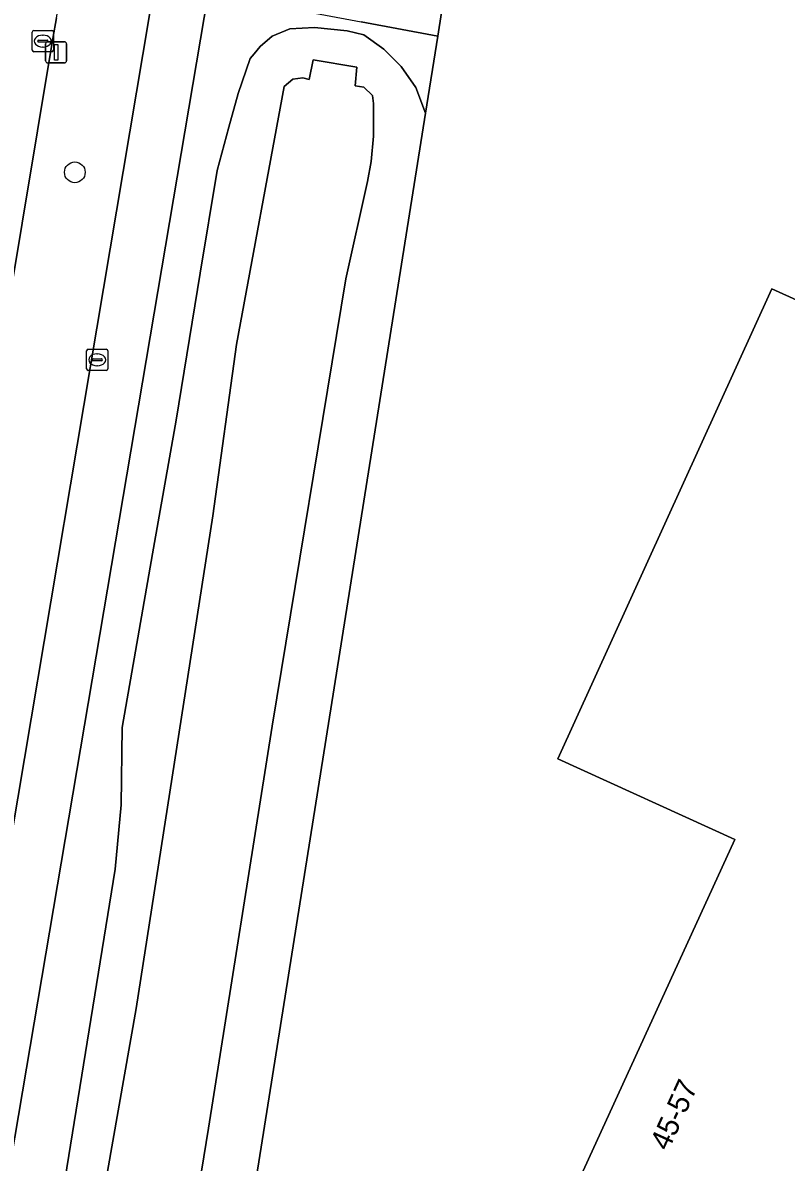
# Model space of a CAD drawing. Extents: x 156141 to 158132, y 385651 to 388333.
# Drawn here: x 156367.7 to 156403.8, y 386609.6 to 386663.4 of the extents above; entities that cross this region are included whole.
import ezdxf

# ---------------------------------------------------------------- set-up
doc = ezdxf.new("R2010")
doc.units = 0
for name, color, linetype in [('IMGEO_Berm_groen', 7, 'Continuous'), ('IMGEO_Boom', 7, 'Continuous'), ('IMGEO_Erf', 7, 'Continuous'), ('IMGEO_Fietspad_gesloten', 7, 'Continuous'), ('IMGEO_Kolk', 7, 'Continuous'), ('IMGEO_Lichtmast', 7, 'Continuous'), ('IMGEO_Muur', 7, 'Continuous'), ('IMGEO_Oever', 7, 'Continuous'), ('IMGEO_Pand', 7, 'Continuous'), ('IMGEO_Pand_nummerreeks', 7, 'Continuous'), ('IMGEO_Rijbaan_lokaal_gesloten', 7, 'Continuous'), ('IMGEO_Rijbaan_lokaal_open', 7, 'Continuous'), ('IMGEO_Rioolput', 7, 'Continuous'), ('IMGEO_Waterloop', 7, 'Continuous')]:
    doc.layers.add(name, color=color, linetype=linetype)

msp = doc.modelspace()

# ---------------------------------------------------------------- linework, layer by layer
at = {"layer": 'IMGEO_Berm_groen'}
for points in [[(156369.305, 386663.658), (156369.141, 386662.678), (156366.222, 386645.225), (156363.399, 386628.51), (156359.75, 386606.622), (156357.341, 386592.608), (156355.257, 386580.281), (156355.517, 386580.234), (156355.483, 386579.181), (156355.759, 386578.249), (156356.674, 386577.611), (156357.605, 386577.179), (156359.068, 386576.796), (156374.013, 386665.695)], [(156376.478, 386664.815), (156361.284, 386575.046)], [(156364.161, 386574.52), (156372.084, 386623.408), (156372.357, 386626.449), (156372.418, 386630.114), (156373.848, 386638.318), (156374.962, 386644.645), (156376.092, 386651.594), (156376.896, 386656.439), (156377.457, 386658.499), (156377.896, 386660.08), (156378.458, 386661.733), (156378.644, 386661.957), (156378.936, 386662.308), (156379.493, 386662.802), (156380.342, 386663.135), (156381.5, 386663.199), (156383.048, 386663.042), (156383.832, 386662.857), (156384.776, 386662.178), (156385.599, 386661.366), (156386.294, 386660.365), (156386.751, 386659.148), (156387.331, 386662.797), (156383.699, 386663.472)]]:
    msp.add_lwpolyline(points, dxfattribs=at)
at = {"layer": 'IMGEO_Boom'}
msp.add_circle((156370.173, 386656.358), 0.489, dxfattribs=at)
at = {"layer": 'IMGEO_Erf'}
for points in [[(156390.282, 386681.033), (156389.3, 386675.585), (156389.197, 386674.913), (156388.457, 386670.11), (156388.273, 386668.916), (156387.331, 386662.797), (156386.751, 386659.148), (156373.047, 386572.88), (156371.992, 386566.952)], [(156423.093, 386572.762), (156425.166, 386577.312), (156417.165, 386580.954), (156415.092, 386576.404), (156414.991, 386576.45), (156398.009, 386584.189), (156397.548, 386583.204), (156386.835, 386588.089), (156387.522, 386589.604), (156386.799, 386591.519), (156385.297, 386592.22), (156390.423, 386603.437), (156391.386, 386602.989), (156401.372, 386624.819), (156392.998, 386628.628), (156403.108, 386650.854), (156419.859, 386643.255), (156422.504, 386649.061), (156456.357, 386633.639), (156453.725, 386627.824), (156470.456, 386620.179), (156458.533, 386594.017), (156466.848, 386590.22), (156458.758, 386572.33)]]:
    msp.add_lwpolyline(points, dxfattribs=at)
at = {"layer": 'IMGEO_Fietspad_gesloten'}
for points in [[(156377.323, 386685.122), (156376.063, 386677.545), (156374.013, 386665.695), (156359.068, 386576.796), (156358.828, 386575.366), (156357.806, 386569.203), (156357.464, 386566.853), (156356.663, 386561.356), (156354.926, 386551.515), (156354.742, 386549.567), (156354.24, 386545.154), (156354.117, 386544.788), (156353.91, 386544.661), (156353.548, 386544.638), (156353.12, 386544.854), (156352.234, 386545.713), (156351.908, 386546.133), (156351.166, 386547.177)], [(156360.26, 386568.995), (156361.284, 386575.046), (156376.478, 386664.815)]]:
    msp.add_lwpolyline(points, dxfattribs=at)
at = {"layer": 'IMGEO_Kolk'}
for p, q in [((156368.159, 386662.137), (156368.159, 386662.989)), ((156368.234, 386663.063), (156369.086, 386663.063)), ((156368.647, 386662.843), (156368.672, 386662.843)), ((156369.16, 386662.989), (156369.16, 386662.137)), ((156368.418, 386662.557), (156368.418, 386662.569)), ((156368.856, 386662.52), (156368.458, 386662.52)), ((156368.461, 386662.606), (156368.859, 386662.606)), ((156368.67, 386662.283), (156368.645, 386662.283)), ((156368.902, 386662.569), (156368.902, 386662.557)), ((156369.086, 386662.063), (156368.234, 386662.063))]:
    msp.add_line(p, q, dxfattribs=at)
for points in [[(156368.159, 386662.137), (156368.159, 386662.989)], [(156368.234, 386663.063), (156369.086, 386663.063)], [(156369.16, 386662.989), (156369.16, 386662.137)], [(156369.086, 386662.063), (156368.234, 386662.063)]]:
    msp.add_lwpolyline(points, dxfattribs=at)
for centre, radius, start, end in [((156368.236, 386662.987), 0.0765, 91.552, 178.448), ((156368.236, 386662.987), 0.0765, 91.552, 178.448), ((156369.084, 386662.987), 0.0765, 1.552, 88.448), ((156369.084, 386662.987), 0.0765, 1.552, 88.448), ((156368.458, 386662.566), 0.0403, 85.8775, 175.7526), ((156368.455, 386662.556), 0.0366, 178.938, 274.7102), ((156368.859, 386662.563), 0.043, 264.8664, 352.4533), ((156368.863, 386662.568), 0.0386, 1.7309, 96.639), ((156368.236, 386662.139), 0.0765, 181.552, 268.448), ((156368.236, 386662.139), 0.0765, 181.552, 268.448), ((156369.084, 386662.139), 0.0765, 271.552, 358.448), ((156369.084, 386662.139), 0.0765, 271.552, 358.448)]:
    msp.add_arc(centre, radius, start, end, dxfattribs=at)
for centre, major_axis, ratio, start_param, end_param in [((156368.646, 386662.563), (-0.387, 0.002), 0.722429, 4.712389, 7.853982), ((156368.671, 386662.563), (-0.39, 0.002), 0.717154, 1.570796, 4.712389)]:
    msp.add_ellipse(centre, major_axis=major_axis, ratio=ratio, start_param=start_param, end_param=end_param, dxfattribs=at)
at = {"layer": 'IMGEO_Lichtmast'}
for p, q in [((156368.794, 386661.632), (156368.794, 386662.432)), ((156368.794, 386662.432), (156368.794, 386661.632)), ((156368.894, 386662.532), (156369.684, 386662.532)), ((156369.684, 386662.532), (156368.894, 386662.532)), ((156369.784, 386662.432), (156369.784, 386661.632)), ((156369.784, 386661.632), (156369.784, 386662.432)), ((156369.684, 386661.532), (156368.894, 386661.532)), ((156368.894, 386661.532), (156369.684, 386661.532))]:
    msp.add_line(p, q, dxfattribs=at)
msp.add_lwpolyline([(156369.214, 386662.407), (156369.364, 386662.407), (156369.364, 386661.657), (156369.214, 386661.657), (156369.214, 386662.407)], dxfattribs=at)
for centre, start, end in [((156368.894, 386662.432), 90, 180), ((156368.894, 386662.432), 90, 180), ((156369.684, 386662.432), 0, 90), ((156369.684, 386662.432), 360, 90), ((156368.894, 386661.632), 180, 270), ((156368.894, 386661.632), 180, 270), ((156369.684, 386661.632), 270, 0), ((156369.684, 386661.632), 270, 0)]:
    msp.add_arc(centre, 0.1, start, end, dxfattribs=at)
at = {"layer": 'IMGEO_Muur'}
msp.add_lwpolyline([(156381.246, 386660.747), (156381.443, 386661.675), (156383.505, 386661.335), (156383.426, 386660.443)], dxfattribs=at)
at = {"layer": 'IMGEO_Oever'}
for points in [[(156373.047, 386572.88), (156386.751, 386659.148), (156386.294, 386660.365), (156385.599, 386661.366), (156384.776, 386662.178), (156383.832, 386662.857), (156383.048, 386663.042), (156381.5, 386663.199), (156380.342, 386663.135), (156379.493, 386662.802), (156378.936, 386662.308), (156378.644, 386661.957), (156378.458, 386661.733), (156377.896, 386660.08), (156377.457, 386658.499), (156376.896, 386656.439), (156376.092, 386651.594), (156374.962, 386644.645), (156373.848, 386638.318), (156372.418, 386630.114), (156372.357, 386626.449), (156372.084, 386623.408), (156364.161, 386574.52)], [(156370.863, 386604.278), (156373.076, 386616.819), (156376.695, 386640.109), (156377.819, 386648.224), (156380.067, 386660.413), (156380.484, 386660.768), (156380.956, 386660.831), (156381.246, 386660.747), (156381.443, 386661.675), (156383.505, 386661.335), (156383.426, 386660.443), (156383.826, 386660.378), (156384.247, 386659.992), (156384.282, 386659.605), (156384.282, 386658.06), (156384.177, 386656.865), (156384.001, 386655.917), (156382.983, 386651.315), (156379.505, 386630.167), (156376.484, 386611.163), (156374.13, 386596.655)]]:
    msp.add_lwpolyline(points, dxfattribs=at)
at = {"layer": 'IMGEO_Pand'}
msp.add_lwpolyline([(156458.758, 386572.33), (156466.848, 386590.22), (156458.533, 386594.017), (156470.456, 386620.179), (156453.725, 386627.824), (156456.357, 386633.639), (156422.504, 386649.061), (156419.859, 386643.255), (156403.108, 386650.854), (156392.998, 386628.628), (156401.372, 386624.819), (156391.386, 386602.989), (156390.423, 386603.437), (156385.297, 386592.22), (156386.799, 386591.519), (156387.522, 386589.604), (156386.835, 386588.089), (156397.548, 386583.204), (156398.009, 386584.189), (156414.991, 386576.45), (156415.092, 386576.404), (156417.165, 386580.954), (156425.166, 386577.312), (156423.093, 386572.762)], dxfattribs=at)
at = {"layer": 'IMGEO_Rijbaan_lokaal_gesloten'}
msp.add_lwpolyline([(156355.014, 386578.858), (156355.161, 386579.716), (156355.257, 386580.281), (156357.341, 386592.608), (156359.75, 386606.622), (156363.399, 386628.51), (156366.222, 386645.225), (156369.141, 386662.678), (156369.305, 386663.658), (156371.343, 386675.841), (156372.272, 386681.317), (156372.444, 386682.329), (156373.065, 386686.117)], dxfattribs=at)
at = {"layer": 'IMGEO_Rijbaan_lokaal_open'}
msp.add_lwpolyline([(156383.699, 386663.472), (156387.331, 386662.797), (156388.273, 386668.916), (156388.457, 386670.11), (156389.197, 386674.913), (156385.668, 386675.625), (156383.698, 386676.023), (156378.55, 386677.062), (156376.478, 386664.815), (156379.049, 386664.337), (156381.763, 386663.832)], close=True, dxfattribs=at)
at = {"layer": 'IMGEO_Rioolput'}
for p, q in [((156370.731, 386647.068), (156370.731, 386647.92)), ((156370.806, 386647.994), (156371.658, 386647.994)), ((156371.219, 386647.774), (156371.244, 386647.774)), ((156371.732, 386647.92), (156371.732, 386647.068)), ((156370.99, 386647.488), (156370.99, 386647.5)), ((156371.428, 386647.451), (156371.03, 386647.451)), ((156371.033, 386647.537), (156371.431, 386647.537)), ((156371.242, 386647.214), (156371.217, 386647.214)), ((156371.474, 386647.5), (156371.474, 386647.488)), ((156371.658, 386646.994), (156370.806, 386646.994))]:
    msp.add_line(p, q, dxfattribs=at)
for points in [[(156370.731, 386647.068), (156370.731, 386647.92)], [(156370.806, 386647.994), (156371.658, 386647.994)], [(156371.732, 386647.92), (156371.732, 386647.068)], [(156371.658, 386646.994), (156370.806, 386646.994)]]:
    msp.add_lwpolyline(points, dxfattribs=at)
for centre, radius, start, end in [((156370.808, 386647.918), 0.0765, 91.552, 178.448), ((156370.808, 386647.918), 0.0765, 91.552, 178.448), ((156371.656, 386647.918), 0.0765, 1.552, 88.448), ((156371.656, 386647.918), 0.0765, 1.552, 88.448), ((156371.03, 386647.497), 0.0403, 85.8775, 175.7526), ((156371.027, 386647.487), 0.0366, 178.938, 274.7102), ((156371.431, 386647.494), 0.043, 264.8664, 352.4533), ((156371.435, 386647.499), 0.0386, 1.7309, 96.639), ((156370.808, 386647.07), 0.0765, 181.552, 268.448), ((156370.808, 386647.07), 0.0765, 181.552, 268.448), ((156371.656, 386647.07), 0.0765, 271.552, 358.448), ((156371.656, 386647.07), 0.0765, 271.552, 358.448)]:
    msp.add_arc(centre, radius, start, end, dxfattribs=at)
for centre, major_axis, ratio, start_param, end_param in [((156371.218, 386647.494), (-0.387, 0.002), 0.722429, 4.712389, 7.853982), ((156371.243, 386647.494), (-0.39, 0.002), 0.717154, 1.570796, 4.712389)]:
    msp.add_ellipse(centre, major_axis=major_axis, ratio=ratio, start_param=start_param, end_param=end_param, dxfattribs=at)
at = {"layer": 'IMGEO_Waterloop'}
msp.add_lwpolyline([(156374.13, 386596.655), (156376.484, 386611.163), (156379.505, 386630.167), (156382.983, 386651.315), (156384.001, 386655.917), (156384.177, 386656.865), (156384.282, 386658.06), (156384.282, 386659.605), (156384.247, 386659.992), (156383.826, 386660.378), (156383.426, 386660.443), (156383.505, 386661.335), (156381.443, 386661.675), (156381.246, 386660.747), (156380.956, 386660.831), (156380.484, 386660.768), (156380.067, 386660.413), (156377.819, 386648.224), (156376.695, 386640.109), (156373.076, 386616.819), (156370.863, 386604.278)], dxfattribs=at)

# ---------------------------------------------------------------- texts
at = {"layer": 'IMGEO_Pand_nummerreeks'}
msp.add_text('45-57', height=1, rotation=65.4186, dxfattribs=at).set_placement((156398.22, 386610.043))

doc.saveas('drawing.dxf')
